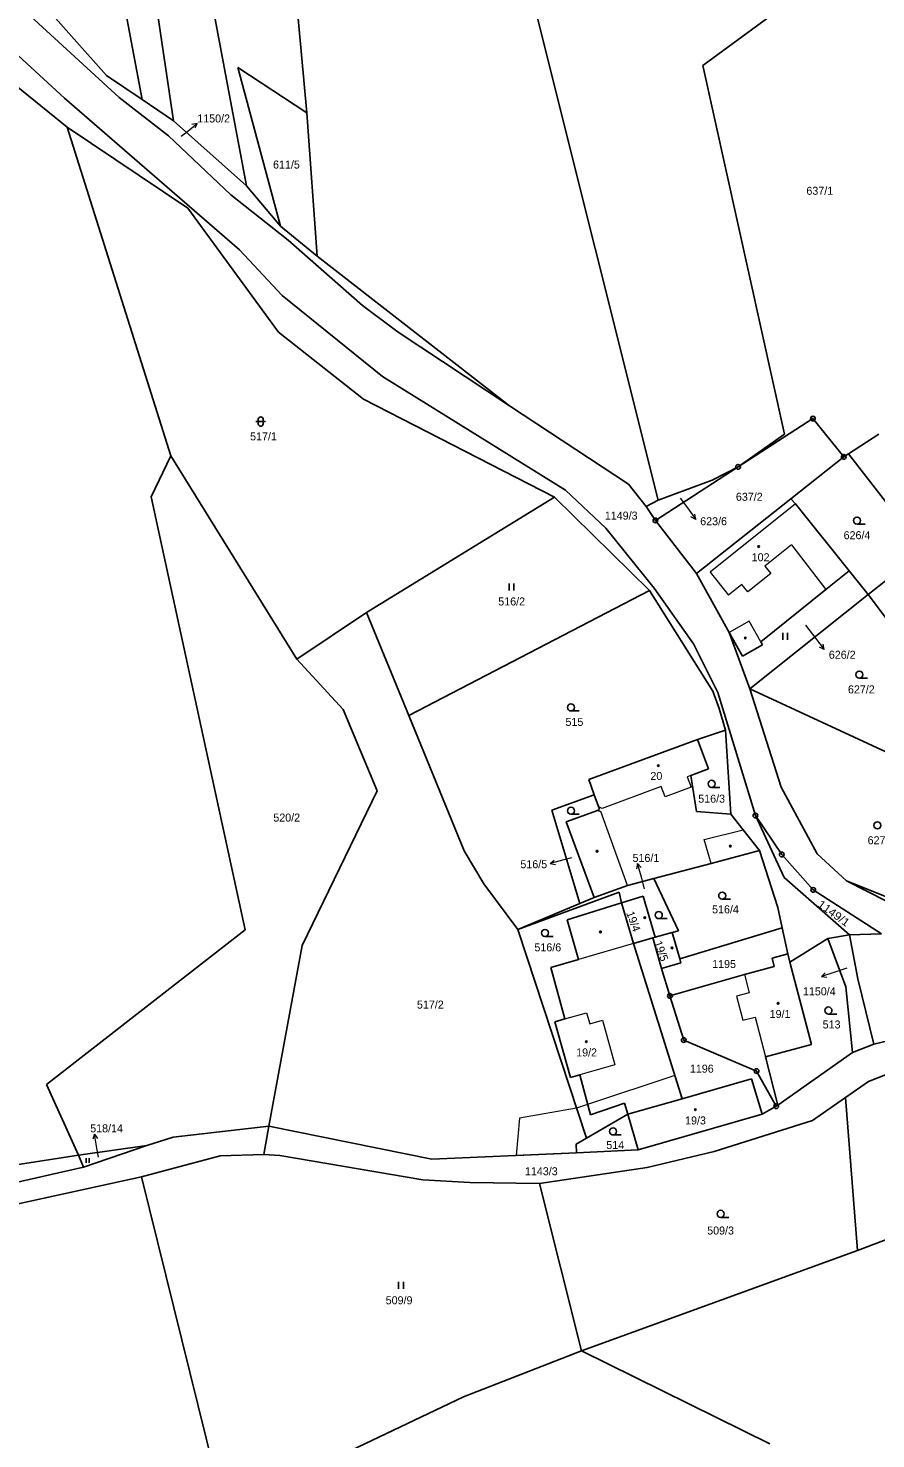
# Model space of a CAD drawing. Extents: x -765428 to -762163, y -1107632 to -1104975.
# Drawn here: x -764503.8 to -764323.7, y -1106034.3 to -1105734.6 of the extents above; entities that cross this region are included whole.
import ezdxf
from ezdxf.enums import TextEntityAlignment as Align

# ---------------------------------------------------------------- set-up
doc = ezdxf.new("R2010")
doc.units = 0
doc.header["$LTSCALE"] = 0.68
for name, color, linetype, lineweight in [('1', 7, 'Continuous', 25), ('13', 7, 'Continuous', 13), ('3', 7, 'Continuous', 25), ('4', 7, 'Continuous', 13), ('5', 7, 'Continuous', 25), ('7', 7, 'Continuous', 13), ('8', 7, 'Continuous', 25)]:
    doc.layers.add(name, color=color, linetype=linetype, lineweight=lineweight)
doc.layers.add('2', color=7, linetype='Continuous')

msp = doc.modelspace()

# ---------------------------------------------------------------- linework, layer by layer
at = {"layer": '1'}
for p, q in [((-764500.73, -1105636.66), (-764479.57, -1105749.82)), ((-764482.13, -1105692.17), (-764472.91, -1105754.34)), ((-764449.12, -1105702.69), (-764444.58, -1105752.61)), ((-764510.46, -1105718.47), (-764487.16, -1105744.67)), ((-764360.47, -1105742.55), (-764326.63, -1105717.75)), ((-764398.74, -1105719.9), (-764369.94, -1105834.93)), ((-764536.41, -1105722.61), (-764495.45, -1105755.7)), ((-764484.43, -1105749.4), (-764505.05, -1105730.47)), ((-764464.77, -1105728.98), (-764457.38, -1105768.14)), ((-764496.07, -1105749.5), (-764510.4, -1105736.36)), ((-764343.13, -1105820.86), (-764360.47, -1105742.55)), ((-764487.16, -1105744.67), (-764479.57, -1105749.82)), ((-764459.21, -1105742.99), (-764444.58, -1105752.61)), ((-764459.21, -1105742.99), (-764450.19, -1105776.67)), ((-764496.07, -1105749.5), (-764458.91, -1105781.73)), ((-764473.94, -1105757.5), (-764484.43, -1105749.4)), ((-764479.57, -1105749.82), (-764472.91, -1105754.34)), ((-764472.91, -1105754.34), (-764457.38, -1105768.14)), ((-764444.58, -1105752.61), (-764442.4, -1105783.1)), ((-764495.45, -1105755.7), (-764469.87, -1105772.9)), ((-764473.45, -1105825.49), (-764495.45, -1105755.7)), ((-764460.72, -1105770.06), (-764473.94, -1105757.5)), ((-764457.38, -1105768.14), (-764450.19, -1105776.67)), ((-764448.54, -1105779.65), (-764460.72, -1105770.06)), ((-764450.58, -1105799.23), (-764469.87, -1105772.9)), ((-764450.19, -1105776.67), (-764442.4, -1105783.1)), ((-764432.76, -1105793.53), (-764448.54, -1105779.65)), ((-764458.91, -1105781.73), (-764449.82, -1105791.44)), ((-764442.4, -1105783.1), (-764401.52, -1105814.86)), ((-764449.82, -1105791.44), (-764428.47, -1105808.66)), ((-764425.2, -1105799.23), (-764432.76, -1105793.53)), ((-764432.57, -1105813.45), (-764450.58, -1105799.23)), ((-764401.52, -1105814.86), (-764425.2, -1105799.23)), ((-764389.6, -1105832.76), (-764428.47, -1105808.66)), ((-764391.95, -1105834.27), (-764432.57, -1105813.45)), ((-764376.24, -1105831.54), (-764401.52, -1105814.86)), ((-764352.95, -1105827.84), (-764337.08, -1105817.58)), ((-764337.08, -1105817.58), (-764330.53, -1105825.71)), ((-764352.95, -1105827.84), (-764343.13, -1105820.86)), ((-764329.52, -1105825.06), (-764323.07, -1105820.91)), ((-764477.61, -1105834.22), (-764473.45, -1105825.49)), ((-764473.45, -1105825.49), (-764446.71, -1105868.67)), ((-764330.53, -1105825.71), (-764341.77, -1105834.6)), ((-764330.53, -1105825.71), (-764329.52, -1105825.06)), ((-764313.6, -1105845.64), (-764329.52, -1105825.06)), ((-764370.51, -1105839.21), (-764352.95, -1105827.84)), ((-764358.45, -1105830.67), (-764352.95, -1105827.84)), ((-764372.52, -1105836.22), (-764376.24, -1105831.54)), ((-764369.94, -1105834.93), (-764358.45, -1105830.67)), ((-764457.67, -1105926.18), (-764477.61, -1105834.22)), ((-764391.95, -1105834.27), (-764431.92, -1105858.74)), ((-764371.77, -1105854.09), (-764391.95, -1105834.27)), ((-764389.6, -1105832.76), (-764381.05, -1105840.89)), ((-764369.94, -1105834.93), (-764372.52, -1105836.22)), ((-764341.77, -1105834.6), (-764361.77, -1105850.46)), ((-764340.79, -1105835.68), (-764341.77, -1105834.6)), ((-764370.51, -1105839.21), (-764372.52, -1105836.22)), ((-764329.35, -1105849.92), (-764340.79, -1105835.68)), ((-764381.05, -1105840.89), (-764370.81, -1105853.61)), ((-764361.77, -1105850.46), (-764370.51, -1105839.21)), ((-764325.31, -1105854.95), (-764313.6, -1105845.64)), ((-764361.77, -1105850.46), (-764354.88, -1105862.99)), ((-764334.3, -1105853.9), (-764329.35, -1105849.92)), ((-764329.35, -1105849.92), (-764325.31, -1105854.95)), ((-764422.94, -1105880.64), (-764371.77, -1105854.09)), ((-764371.77, -1105854.09), (-764358.33, -1105875.45)), ((-764370.81, -1105853.61), (-764362.41, -1105865.41)), ((-764350.48, -1105874.96), (-764325.31, -1105854.95)), ((-764348.13, -1105865.01), (-764334.3, -1105853.9)), ((-764446.71, -1105868.67), (-764431.92, -1105858.74)), ((-764431.92, -1105858.74), (-764422.94, -1105880.64)), ((-764362.41, -1105865.41), (-764357.25, -1105875.79)), ((-764350.48, -1105874.96), (-764354.88, -1105862.99)), ((-764354.88, -1105862.99), (-764352.04, -1105868.03)), ((-764347.78, -1105865.63), (-764348.13, -1105865.01)), ((-764347.78, -1105865.63), (-764352.04, -1105868.03)), ((-764446.71, -1105868.67), (-764436.88, -1105879.4)), ((-764357.01, -1105879.15), (-764358.33, -1105875.45)), ((-764357.25, -1105875.79), (-764349.27, -1105901.9)), ((-764343.78, -1105895.85), (-764350.48, -1105874.96)), ((-764350.48, -1105874.96), (-764318.67, -1105889.74)), ((-764436.88, -1105879.4), (-764429.6, -1105896.63)), ((-764355.61, -1105883.75), (-764357.01, -1105879.15)), ((-764422.94, -1105880.64), (-764411.14, -1105909.42)), ((-764384.69, -1105894.26), (-764361.58, -1105885.74)), ((-764361.58, -1105885.74), (-764355.61, -1105883.75)), ((-764361.58, -1105885.74), (-764359.22, -1105891.99)), ((-764354.48, -1105901.63), (-764355.61, -1105883.75)), ((-764363, -1105893.39), (-764359.22, -1105891.99)), ((-764383.52, -1105897.54), (-764384.69, -1105894.26)), ((-764361.83, -1105901.02), (-764363, -1105893.39)), ((-764429.6, -1105896.63), (-764445.58, -1105929.5)), ((-764392.56, -1105900.73), (-764383.52, -1105897.54)), ((-764382.65, -1105900), (-764383.52, -1105897.54)), ((-764336.15, -1105910.04), (-764343.78, -1105895.85)), ((-764392.56, -1105900.73), (-764386.6, -1105920.57)), ((-764382.84, -1105900.8), (-764389.51, -1105903.27)), ((-764382.84, -1105900.8), (-764382.42, -1105900.64)), ((-764382.42, -1105900.64), (-764382.65, -1105900)), ((-764354.48, -1105901.63), (-764361.83, -1105901.02)), ((-764389.51, -1105903.27), (-764383.57, -1105919.29)), ((-764351.89, -1105904.93), (-764354.48, -1105901.63)), ((-764343.7, -1105910.18), (-764349.27, -1105901.9)), ((-764349.27, -1105901.9), (-764343.17, -1105915.06)), ((-764348.44, -1105909.32), (-764351.89, -1105904.93)), ((-764406.99, -1105916.4), (-764411.14, -1105909.42)), ((-764348.44, -1105909.32), (-764358.69, -1105912.09)), ((-764344.55, -1105921.43), (-764348.44, -1105909.32)), ((-764337.01, -1105917.71), (-764343.7, -1105910.18)), ((-764329.92, -1105915.78), (-764336.15, -1105910.04)), ((-764358.69, -1105912.09), (-764370.88, -1105915.27)), ((-764399.75, -1105926.13), (-764406.99, -1105916.4)), ((-764370.88, -1105915.27), (-764376.46, -1105916.73)), ((-764365.59, -1105926.41), (-764370.88, -1105915.27)), ((-764343.17, -1105915.06), (-764329.29, -1105927.24)), ((-764310.49, -1105925.64), (-764329.92, -1105915.78)), ((-764319.54, -1105919.98), (-764329.92, -1105915.78)), ((-764399.75, -1105926.13), (-764378.24, -1105918.18)), ((-764383.57, -1105919.29), (-764386.6, -1105920.57)), ((-764376.46, -1105916.73), (-764383.57, -1105919.29)), ((-764373.16, -1105919.04), (-764377.76, -1105920.46)), ((-764370.55, -1105927.73), (-764373.16, -1105919.04)), ((-764322.47, -1105927.06), (-764337.01, -1105917.71)), ((-764386.6, -1105920.57), (-764399.75, -1105926.13)), ((-764377.76, -1105920.46), (-764389.28, -1105924.03)), ((-764343.62, -1105925.79), (-764344.55, -1105921.43)), ((-764389.28, -1105924.03), (-764386.83, -1105932.46)), ((-764499.88, -1105959.02), (-764457.67, -1105926.18)), ((-764385.18, -1105970.46), (-764399.75, -1105926.13)), ((-764375.19, -1105929.08), (-764371.04, -1105927.87)), ((-764371.04, -1105927.87), (-764370.55, -1105927.73)), ((-764369.26, -1105934.37), (-764371.04, -1105927.87)), ((-764370.55, -1105927.73), (-764366.94, -1105926.78)), ((-764366.94, -1105926.78), (-764365.59, -1105926.41)), ((-764366.94, -1105926.78), (-764365.35, -1105932.35)), ((-764365.35, -1105932.35), (-764343.62, -1105925.79)), ((-764342.37, -1105931.28), (-764343.62, -1105925.79)), ((-764341.94, -1105933.03), (-764333.87, -1105928.03)), ((-764329.29, -1105927.24), (-764333.87, -1105928.03)), ((-764330.07, -1105938.31), (-764333.87, -1105928.03)), ((-764322.47, -1105927.06), (-764329.29, -1105927.24)), ((-764329.29, -1105927.24), (-764327.52, -1105936.61)), ((-764445.58, -1105929.5), (-764452.62, -1105967.87)), ((-764364.87, -1105962.05), (-764375.19, -1105929.08)), ((-764342.37, -1105931.28), (-764345.73, -1105932.2)), ((-764341.94, -1105933.03), (-764342.37, -1105931.28)), ((-764392.72, -1105934.21), (-764386.83, -1105932.46)), ((-764392.72, -1105934.21), (-764389.79, -1105945.12)), ((-764365.15, -1105933.21), (-764369.26, -1105934.37)), ((-764367.43, -1105940.23), (-764369.26, -1105934.37)), ((-764365.35, -1105932.35), (-764365.15, -1105933.21)), ((-764345.29, -1105933.94), (-764351.61, -1105935.66)), ((-764345.73, -1105932.2), (-764345.29, -1105933.94)), ((-764337.38, -1105950.57), (-764341.94, -1105933.03)), ((-764367.43, -1105940.23), (-764351.61, -1105935.66)), ((-764327.52, -1105936.61), (-764324.11, -1105950.49)), ((-764364.52, -1105949.59), (-764367.43, -1105940.23)), ((-764328.63, -1105952.26), (-764330.07, -1105938.31)), ((-764391.92, -1105945.73), (-764389.79, -1105945.12)), ((-764388.56, -1105957.54), (-764391.92, -1105945.73)), ((-764324.11, -1105950.49), (-764316.03, -1105948.56)), ((-764349.03, -1105956.19), (-764364.52, -1105949.59)), ((-764347.16, -1105953.14), (-764337.38, -1105950.57)), ((-764344.49, -1105963.45), (-764328.63, -1105952.26)), ((-764328.63, -1105952.26), (-764324.11, -1105950.49)), ((-764344.49, -1105963.45), (-764347.16, -1105953.14)), ((-764325.28, -1105958.41), (-764311.58, -1105952.95)), ((-764386.61, -1105956.99), (-764388.56, -1105957.54)), ((-764386.61, -1105956.99), (-764384.34, -1105965.46)), ((-764350.14, -1105957.81), (-764364.87, -1105962.05)), ((-764347.86, -1105965.33), (-764350.14, -1105957.81)), ((-764344.87, -1105963.66), (-764349.03, -1105956.19)), ((-764330.16, -1105961.82), (-764325.28, -1105958.41)), ((-764493.07, -1105974.05), (-764499.88, -1105959.02)), ((-764384.34, -1105965.46), (-764377.07, -1105963.01)), ((-764376.39, -1105965.37), (-764377.07, -1105963.01)), ((-764364.87, -1105962.05), (-764376.39, -1105965.37)), ((-764344.87, -1105963.66), (-764347.86, -1105965.33)), ((-764344.87, -1105963.66), (-764344.49, -1105963.45)), ((-764337.13, -1105966.69), (-764330.16, -1105961.82)), ((-764327.63, -1105994.29), (-764330.16, -1105961.82)), ((-764376.39, -1105965.37), (-764385.18, -1105970.46)), ((-764376.39, -1105965.37), (-764374.21, -1105972.92)), ((-764374.21, -1105972.92), (-764347.86, -1105965.33)), ((-764358.07, -1105973.28), (-764337.13, -1105966.69)), ((-764478.58, -1105972.01), (-764473, -1105970.24)), ((-764473, -1105970.24), (-764452.62, -1105967.87)), ((-764452.62, -1105967.87), (-764453.73, -1105973.94)), ((-764418.04, -1105974.93), (-764452.62, -1105967.87)), ((-764493.07, -1105974.05), (-764478.58, -1105972.01)), ((-764492, -1105976.6), (-764478.58, -1105972.01)), ((-764387.37, -1105971.73), (-764385.18, -1105970.46)), ((-764387.37, -1105971.73), (-764387.27, -1105973.58)), ((-764374.21, -1105972.92), (-764387.27, -1105973.58)), ((-764372.27, -1105976.64), (-764358.07, -1105973.28)), ((-764602.38, -1105990.99), (-764493.07, -1105974.05)), ((-764493.07, -1105974.05), (-764492, -1105976.6)), ((-764462.97, -1105974.19), (-764479.66, -1105978.64)), ((-764453.73, -1105973.94), (-764462.97, -1105974.19)), ((-764453.73, -1105973.94), (-764450.28, -1105974.11)), ((-764450.28, -1105974.11), (-764419.9, -1105979.26)), ((-764387.27, -1105973.58), (-764418.04, -1105974.93)), ((-764479.66, -1105978.64), (-764536.86, -1105991.14)), ((-764532.53, -1105985.7), (-764492, -1105976.6)), ((-764479.66, -1105978.64), (-764463.45, -1106044.21)), ((-764419.9, -1105979.26), (-764409.95, -1105979.87)), ((-764395.13, -1105980.08), (-764372.27, -1105976.64)), ((-764409.95, -1105979.87), (-764395.13, -1105980.08)), ((-764386.26, -1106015.6), (-764395.13, -1105980.08)), ((-764294.95, -1105981.82), (-764327.63, -1105994.29)), ((-764327.63, -1105994.29), (-764386.26, -1106015.6)), ((-764386.26, -1106015.6), (-764411.29, -1106025.42)), ((-764386.26, -1106015.6), (-764346.19, -1106035.37)), ((-764411.29, -1106025.42), (-764464.92, -1106050.85))]:
    msp.add_line(p, q, dxfattribs=at)
for points in [[(-764325.31, -1105854.95), (-764308.1, -1105877.84), (-764318.67, -1105889.74)], [(-764378.24, -1105918.18), (-764377.76, -1105920.46), (-764375.19, -1105929.08)]]:
    msp.add_lwpolyline(points, dxfattribs=at)
at = {"layer": '13'}
msp.add_lwpolyline([(-764400.14, -1105974.14), (-764387.27, -1105973.58), (-764387.37, -1105971.73), (-764385.18, -1105970.46), (-764376.39, -1105965.37), (-764364.87, -1105962.05), (-764366.41, -1105957.12), (-764384.92, -1105963.29), (-764387.28, -1105964.08), (-764399.39, -1105966.19)], close=True, dxfattribs=at)
at = {"layer": '3'}
for p, q in [((-764455.381, -1105818.211), (-764453.379, -1105818.211)), ((-764454.881, -1105817.711), (-764454.881, -1105818.712)), ((-764453.879, -1105818.712), (-764453.879, -1105817.711)), ((-764327.703, -1105840), (-764325.953, -1105840)), ((-764401.581, -1105854.1), (-764401.581, -1105852.6)), ((-764400.58, -1105854.1), (-764400.58, -1105852.6)), ((-764343.471, -1105864.58), (-764343.471, -1105863.08)), ((-764342.47, -1105864.58), (-764342.47, -1105863.08)), ((-764327.203, -1105872.72), (-764325.453, -1105872.72)), ((-764388.473, -1105879.69), (-764386.723, -1105879.69)), ((-764358.593, -1105895.92), (-764356.843, -1105895.92)), ((-764388.463, -1105901.63), (-764386.713, -1105901.63)), ((-764356.333, -1105919.68), (-764354.583, -1105919.68)), ((-764369.813, -1105923.81), (-764368.063, -1105923.81)), ((-764393.983, -1105927.59), (-764392.233, -1105927.59)), ((-764333.773, -1105944.07), (-764332.023, -1105944.07)), ((-764379.523, -1105969.76), (-764377.773, -1105969.76)), ((-764491.462, -1105975.68), (-764491.462, -1105974.675)), ((-764490.792, -1105975.68), (-764490.792, -1105974.675)), ((-764356.663, -1105987.27), (-764354.913, -1105987.27)), ((-764425.071, -1106002.47), (-764425.071, -1106000.97)), ((-764424.07, -1106002.47), (-764424.07, -1106000.97))]:
    msp.add_line(p, q, dxfattribs=at)
for centre in [(-764327.7029, -1105839.2498), (-764327.2029, -1105871.9698), (-764388.4729, -1105878.9398), (-764358.5929, -1105895.1698), (-764388.4629, -1105900.8798), (-764323.3729, -1105903.9898), (-764356.3329, -1105918.9298), (-764369.8129, -1105923.0598), (-764393.9829, -1105926.8398), (-764333.7729, -1105943.3198), (-764379.5229, -1105969.0098), (-764356.6629, -1105986.5198)]:
    msp.add_circle(centre, 0.75, dxfattribs=at)
for centre, start, end in [((-764454.38, -1105817.7109), 0, 180), ((-764454.38, -1105818.7109), 180, 359.98789)]:
    msp.add_arc(centre, 0.5, start, end, dxfattribs=at)
at = {"layer": '4'}
for p, q in [((-764340.79, -1105835.68), (-764358.93, -1105850.21)), ((-764341.65, -1105844.41), (-764334.3, -1105853.9)), ((-764358.93, -1105850.21), (-764355.01, -1105855.12)), ((-764350.62, -1105860.59), (-764354.88, -1105862.99)), ((-764348.13, -1105865.01), (-764350.62, -1105860.59)), ((-764363, -1105893.39), (-764363.79, -1105893.69)), ((-764363.79, -1105893.69), (-764362.95, -1105895.88)), ((-764369.27, -1105895.73), (-764381.83, -1105900.4)), ((-764368.45, -1105897.93), (-764369.27, -1105895.73)), ((-764362.95, -1105895.88), (-764368.45, -1105897.93)), ((-764382.84, -1105900.8), (-764382.1, -1105901.07)), ((-764381.83, -1105900.4), (-764382.65, -1105900)), ((-764376.46, -1105916.73), (-764382.1, -1105901.07)), ((-764360.14, -1105906.96), (-764351.89, -1105904.93)), ((-764358.69, -1105912.09), (-764360.14, -1105906.96)), ((-764375.19, -1105929.08), (-764386.83, -1105932.46)), ((-764351.61, -1105935.66), (-764350.62, -1105939.55)), ((-764350.62, -1105939.55), (-764353.3, -1105940.25)), ((-764353.3, -1105940.25), (-764351.96, -1105945.38)), ((-764389.79, -1105945.12), (-764385.14, -1105943.8)), ((-764385.14, -1105943.8), (-764384.48, -1105946.12)), ((-764384.48, -1105946.12), (-764381.8, -1105945.38)), ((-764381.8, -1105945.38), (-764379.12, -1105954.86)), ((-764351.96, -1105945.38), (-764349.35, -1105944.7)), ((-764349.35, -1105944.7), (-764347.16, -1105953.14)), ((-764379.12, -1105954.86), (-764386.61, -1105956.99))]:
    msp.add_line(p, q, dxfattribs=at)
msp.add_lwpolyline([(-764341.65, -1105844.41), (-764347.29, -1105848.93), (-764346.03, -1105850.5), (-764350.88, -1105854.39), (-764352.14, -1105852.82), (-764355.01, -1105855.12)], dxfattribs=at)
at = {"layer": '5'}
for centre in [(-764348.5768, -1105844.7592), (-764351.4268, -1105864.1892), (-764369.9168, -1105891.3092), (-764382.9068, -1105909.4892), (-764354.6068, -1105908.3992), (-764372.7868, -1105923.5892), (-764382.2068, -1105926.6192), (-764367.0168, -1105930.0092), (-764344.4568, -1105941.7792), (-764385.1868, -1105949.9492), (-764362.0368, -1105964.3992)]:
    msp.add_circle(centre, 0.175, dxfattribs=at)
at = {"layer": '7'}
for p, q in [((-764467.878, -1105754.881), (-764468.971, -1105755.123)), ((-764361.976, -1105838.998), (-764362.16, -1105837.893)), ((-764334.694, -1105866.617), (-764334.897, -1105865.516)), ((-764392.849, -1105912.107), (-764391.752, -1105912.331)), ((-764374.337, -1105912.115), (-764374.542, -1105913.216)), ((-764335.254, -1105936.087), (-764334.147, -1105936.254)), ((-764489.681, -1105969.605), (-764490, -1105970.678))]:
    msp.add_line(p, q, dxfattribs=at)
for points in [[(-764471.25, -1105757.61), (-764470.21, -1105756.77), (-764467.878, -1105754.881), (-764468.341, -1105755.901)], [(-764365.28, -1105834.47), (-764363.74, -1105836.57), (-764361.976, -1105838.998), (-764362.97, -1105838.482)], [(-764338.61, -1105861.45), (-764336.5, -1105864.22), (-764334.694, -1105866.617), (-764335.697, -1105866.118)], [(-764388.37, -1105910.91), (-764389.95, -1105911.33), (-764392.849, -1105912.107), (-764392.011, -1105911.364)], [(-764372.81, -1105917.46), (-764373.51, -1105915), (-764374.337, -1105912.115), (-764373.58, -1105912.94)], [(-764329.86, -1105934.32), (-764332.4, -1105935.16), (-764335.254, -1105936.087), (-764334.456, -1105935.302)], [(-764488.81, -1105974.48), (-764489.16, -1105972.56), (-764489.681, -1105969.605), (-764489.014, -1105970.504)]]:
    msp.add_lwpolyline(points, dxfattribs=at)
at = {"layer": '8'}
for centre, radius in [((-764337.08, -1105817.5799), 0.5), ((-764337.08, -1105817.5799), 0.0303), ((-764330.53, -1105825.7099), 0.5), ((-764330.53, -1105825.7099), 0.0303), ((-764352.95, -1105827.8399), 0.5), ((-764352.95, -1105827.8399), 0.0303), ((-764370.51, -1105839.2099), 0.5), ((-764370.51, -1105839.2099), 0.0303), ((-764349.27, -1105901.8999), 0.5), ((-764349.27, -1105901.8999), 0.0303), ((-764343.7, -1105910.1799), 0.5), ((-764343.7, -1105910.1799), 0.0303), ((-764337.01, -1105917.7099), 0.5), ((-764337.01, -1105917.7099), 0.0303), ((-764367.43, -1105940.2299), 0.5), ((-764367.43, -1105940.2299), 0.0303), ((-764364.52, -1105949.5899), 0.5), ((-764364.52, -1105949.5899), 0.0303), ((-764349.03, -1105956.1899), 0.5), ((-764349.03, -1105956.1899), 0.0303), ((-764344.87, -1105963.6599), 0.5), ((-764344.87, -1105963.6599), 0.0303)]:
    msp.add_circle(centre, radius, dxfattribs=at)

# ---------------------------------------------------------------- texts
at = {"layer": '2'}
for s, p in [('1150/2', (-764467.85, -1105754.675)), ('517/1', (-764456.63, -1105822.205)), ('637/2', (-764353.43, -1105835.045)), ('623/6', (-764361.01, -1105840.235)), ('626/4', (-764330.55, -1105843.205)), ('102', (-764350.08, -1105847.885)), ('516/2', (-764403.91, -1105857.275)), ('626/2', (-764333.69, -1105868.595)), ('627/2', (-764329.63, -1105875.955)), ('515', (-764389.63, -1105882.855)), ('20', (-764371.59, -1105894.355)), ('516/3', (-764361.43, -1105899.175)), ('520/2', (-764451.69, -1105903.185)), ('627/1', (-764325.45, -1105908.005)), ('516/4', (-764358.49, -1105922.675)), ('516/6', (-764396.23, -1105930.755)), ('517/2', (-764421.18, -1105942.915)), ('19/1', (-764346.26, -1105944.905)), ('513', (-764335, -1105947.135)), ('19/2', (-764387.36, -1105953.075)), ('1196', (-764363.2, -1105956.525)), ('19/3', (-764364.22, -1105967.525)), ('514', (-764380.96, -1105972.745)), ('1143/3', (-764398.24, -1105978.315)), ('509/3', (-764359.53, -1105990.905)), ('509/9', (-764427.82, -1106005.725))]:
    msp.add_text(s, height=1.7, dxfattribs=at).set_placement(p)
for s, p in [('611/5', (-764448.91, -1105764.465)), ('637/1', (-764335.61, -1105770.035)), ('1149/3', (-764377.8, -1105839.035)), ('1195', (-764355.94, -1105934.295))]:
    msp.add_text(s, height=1.7, dxfattribs=at).set_placement(p, align=Align.CENTER)
for s, p in [('516/1', (-764369.7, -1105911.755)), ('516/5', (-764393.52, -1105913.095)), ('1150/4', (-764332.239, -1105940.095)), ('518/14', (-764483.639, -1105969.205))]:
    msp.add_text(s, height=1.7, dxfattribs=at).set_placement(p, align=Align.RIGHT)
for s, p in [('19/4', (-764376.749, -1105922.595)), ('19/5', (-764370.839, -1105928.885))]:
    msp.add_text(s, height=1.7, rotation=290, dxfattribs=at).set_placement(p)
at = {"layer": '2', "width": 1.1}
msp.add_text('1149/1', height=1.7, rotation=324, dxfattribs=at).set_placement((-764333.1351, -1105923.3484), align=Align.CENTER)

doc.saveas('drawing.dxf')
